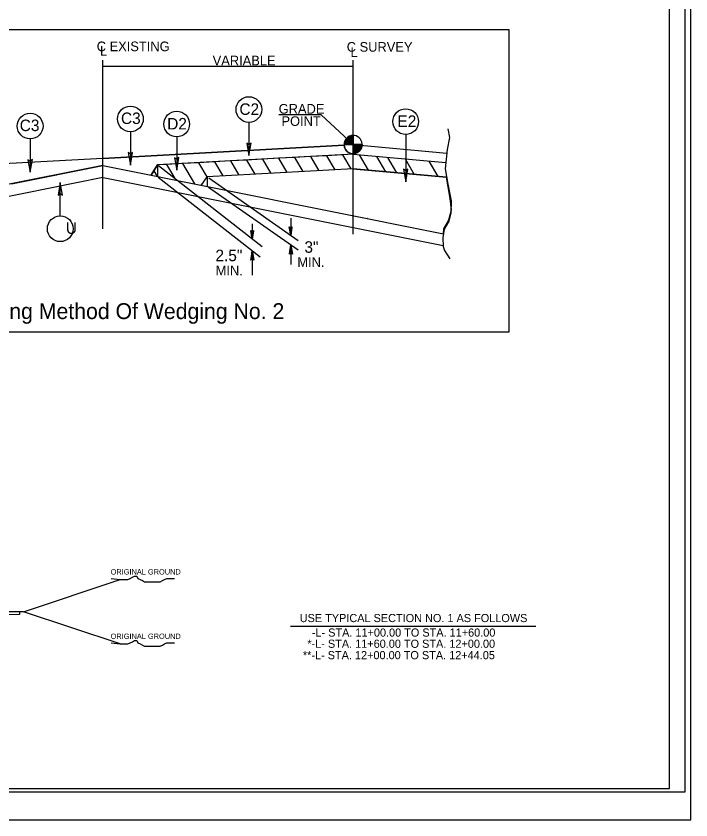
# Model space of a CAD drawing. Extents: x 957297 to 961629, y 830661 to 840840.
# Drawn here: x 959856 to 960395, y 839740 to 840382 of the extents above; entities that cross this region are included whole.
import ezdxf

# ---------------------------------------------------------------- set-up
doc = ezdxf.new("R2010")
doc.units = 0
for name, color, linetype in [('Old_Level_1', 7, 'Continuous'), ('Old_Level_21', 7, 'Continuous'), ('Sheet Plot Border Inside CELL', 7, 'Continuous'), ('Sheet Plot Border Outside CELL', 7, 'Continuous'), ('Sheet Typical CELL', 7, 'Continuous'), ('Typical Detail Wedge1 CELL', 7, 'Continuous'), ('Typical Grade Point Symbol CELL', 7, 'Continuous'), ('Typical ID Circle CELL', 7, 'Continuous'), ('Typical Terminator CELL', 7, 'Continuous'), ('Typical Text Centerline CELL', 7, 'Continuous'), ('Typical Text General CELL', 7, 'Continuous'), ('Typical Text Grade Point CELL', 7, 'Continuous'), ('Typical Text ID Circle CELL', 7, 'Continuous')]:
    doc.layers.add(name, color=color, linetype=linetype)

msp = doc.modelspace()

# ---------------------------------------------------------------- linework, layer by layer
at = {"layer": 'Old_Level_1'}
for p, q in [((959861.75, 839906), (959938.93, 839931.73)), ((959861.75, 839906), (959798.79, 839905.37)), ((959858.45, 839903.79), (959825.43, 839903.46)), ((959858.45, 839905.97), (959858.45, 839903.79)), ((959938.93, 839880.27), (959861.75, 839906)), ((960075.05, 839894.58), (960270.99, 839894.58))]:
    msp.add_line(p, q, dxfattribs=at)
msp.add_lwpolyline([(960249.58, 840370.75), (959623.52, 840370.75), (959623.52, 840129.62), (960249.58, 840129.62)], close=True, dxfattribs=at)
at = {"layer": 'Old_Level_21'}
for points in [[(959931.84, 839932.61), (959938.93, 839931.73), (959940.71, 839931.73), (959943.37, 839931.73), (959945.15, 839931.73), (959946.92, 839932.61), (959948.69, 839933.51), (959950.46, 839934.39), (959952.24, 839934.39), (959953.14, 839932.61), (959954.9, 839931.73), (959956.68, 839930.84), (959958.45, 839929.96), (959960.22, 839929.96), (959961.99, 839929.96), (959963.77, 839929.96), (959965.54, 839929.96), (959967.32, 839929.96), (959969.09, 839929.96), (959970.86, 839929.96), (959972.63, 839930.84), (959974.4, 839931.73), (959976.17, 839932.61), (959978.85, 839932.61), (959980.62, 839932.61), (959982.39, 839932.61)], [(959931.84, 839881.15), (959938.93, 839880.27), (959940.71, 839880.27), (959943.37, 839880.27), (959945.15, 839880.27), (959946.92, 839881.15), (959948.69, 839882.05), (959950.46, 839882.93), (959952.24, 839882.93), (959953.14, 839881.15), (959954.9, 839880.27), (959956.68, 839879.37), (959958.45, 839878.5), (959960.22, 839878.5), (959961.99, 839878.5), (959963.77, 839878.5), (959965.54, 839878.5), (959967.32, 839878.5), (959969.09, 839878.5), (959970.86, 839878.5), (959972.63, 839879.37), (959974.4, 839880.27), (959976.17, 839881.15), (959978.85, 839881.15), (959980.62, 839881.15), (959982.39, 839881.15)]]:
    msp.add_lwpolyline(points, dxfattribs=at)
at = {"layer": 'Sheet Plot Border Inside CELL'}
msp.add_lwpolyline([(960390.3, 840817.27), (958723.8, 840817.27), (958723.8, 839762.17), (960390.3, 839762.17)], close=True, dxfattribs=at)
at = {"layer": 'Sheet Plot Border Outside CELL'}
msp.add_lwpolyline([(960394.8, 840839.72), (958710.8, 840839.72), (958710.8, 839739.72), (960394.8, 839739.72)], close=True, dxfattribs=at)
at = {"layer": 'Sheet Typical CELL'}
msp.add_lwpolyline([(960377.8, 840814.72), (958877.8, 840814.72), (958877.8, 839764.72), (960377.8, 839764.72)], close=True, dxfattribs=at)
at = {"layer": 'Typical Detail Wedge1 CELL'}
for p, q in [((959925.21, 840211.84), (959925.21, 840346.6)), ((960125.03, 840279.09), (960125.03, 840346.65)), ((960125.03, 840341.47), (959925.21, 840341.47)), ((960117.75, 840278.69), (959925.21, 840268.1)), ((959925.21, 840268.1), (960117.75, 840278.69)), ((960125.03, 840279.09), (960125.02, 840271.39)), ((960125.03, 840279.09), (960199.77, 840272.36)), ((959925.21, 840268.1), (959692.59, 840255.33)), ((959925.21, 840268.1), (959692.59, 840255.33)), ((959925.21, 840262.34), (959925.21, 840268.1)), ((959925.21, 840262.34), (959925.21, 840268.1)), ((960125.02, 840271.39), (959968.84, 840262.81)), ((960052.72, 840267.42), (960039.94, 840266.72)), ((960065.5, 840268.13), (960052.72, 840267.42)), ((960052.72, 840267.42), (960059.3, 840256.14)), ((960078.27, 840268.82), (960065.5, 840268.13)), ((960065.5, 840268.13), (960072.08, 840256.84)), ((960091.05, 840269.53), (960078.27, 840268.82)), ((960078.27, 840268.82), (960084.86, 840257.55)), ((960103.82, 840270.24), (960091.05, 840269.53)), ((960091.05, 840269.53), (960097.63, 840258.25)), ((960116.6, 840270.93), (960103.82, 840270.24)), ((960103.82, 840270.24), (960110.41, 840258.96)), ((960125.02, 840271.39), (960116.6, 840270.93)), ((960116.6, 840270.93), (960123.17, 840259.65)), ((960124.98, 840271.93), (960125.02, 840271.39)), ((960125.02, 840271.39), (960198.98, 840264.74)), ((960125.02, 840271.39), (960198.96, 840264.74)), ((960125.03, 840207.61), (960125.03, 840271.93)), ((960129.76, 840270.96), (960136.96, 840258.62)), ((960143.68, 840269.71), (960150.89, 840257.36)), ((960152.56, 840268.92), (960159.75, 840256.6)), ((960166.49, 840267.66), (960173.7, 840255.3)), ((959925.21, 840262.34), (959697.32, 840216.87)), ((959852.13, 840247.71), (959925.21, 840262.34)), ((959925.21, 840262.34), (960197.19, 840207.94)), ((959963.55, 840254.54), (959968.84, 840262.81)), ((959968.84, 840262.81), (959963.62, 840254.65)), ((959976.07, 840263.22), (959968.84, 840262.81)), ((959968.84, 840262.81), (959968.84, 840253.61)), ((959969.46, 840262.28), (960052.28, 840197.58)), ((959988.84, 840263.91), (959976.07, 840263.22)), ((959976.07, 840263.22), (959983.36, 840250.71)), ((960001.62, 840264.6), (959988.84, 840263.91)), ((959988.84, 840263.91), (959998.29, 840247.73)), ((960014.38, 840265.31), (960001.62, 840264.6)), ((960001.62, 840264.6), (960008.2, 840253.34)), ((960027.17, 840266.02), (960014.38, 840265.31)), ((960014.38, 840265.31), (960020.97, 840254.03)), ((960039.94, 840266.72), (960027.17, 840266.02)), ((960027.17, 840266.02), (960033.74, 840254.74)), ((960039.94, 840266.72), (960046.53, 840255.44)), ((960185.43, 840265.95), (960192.63, 840253.6)), ((959965.85, 840258.15), (959968.44, 840253.7)), ((960125.03, 840259.76), (960008.46, 840253.34)), ((960125.03, 840259.76), (960008.47, 840253.34)), ((960124.86, 840259.7), (960199.69, 840252.96)), ((960199.69, 840252.96), (960125.03, 840259.76)), ((959925.21, 840252.71), (959697.03, 840207.06)), ((959925.42, 840252.71), (960196.8, 840198.43)), ((959969.39, 840253.13), (960050.75, 840189.56)), ((960003.6, 840246.49), (960008.47, 840253.34)), ((960008.46, 840253.34), (960008.46, 840245.69)), ((960009.68, 840252.5), (960081.22, 840202.41)), ((960202.54, 840236.15), (960199.69, 840252.96)), ((960009.44, 840245.19), (960081.1, 840195)), ((960203.58, 840226.88), (960202.54, 840236.15)), ((960201.51, 840218.98), (960203.58, 840226.88)), ((960044.46, 840215.76), (960044.46, 840203.68)), ((960075.22, 840220.34), (960075.22, 840206.61)), ((960197.39, 840212.12), (960201.51, 840218.98)), ((960044.46, 840203.68), (960043.26, 840210.44)), ((960043.26, 840210.44), (960044.46, 840209.56)), ((960043.43, 840210.31), (960044.46, 840203.68)), ((960044.46, 840203.68), (960043.61, 840210.18)), ((960043.78, 840210.07), (960044.46, 840203.68)), ((960044.46, 840203.68), (960043.95, 840209.94)), ((960044.12, 840209.81), (960044.46, 840203.68)), ((960044.46, 840203.68), (960044.29, 840209.68)), ((960044.46, 840203.68), (960045.65, 840210.44)), ((960044.46, 840209.56), (960045.65, 840210.44)), ((960044.46, 840203.68), (960045.48, 840210.31)), ((960045.31, 840210.18), (960044.46, 840203.68)), ((960044.46, 840203.68), (960045.14, 840210.07)), ((960044.97, 840209.94), (960044.46, 840203.68)), ((960044.46, 840203.68), (960044.8, 840209.81)), ((960044.62, 840209.68), (960044.46, 840203.68)), ((960044.46, 840209.56), (960044.46, 840203.68)), ((960075.22, 840206.61), (960074.02, 840213.37)), ((960074.02, 840213.37), (960075.22, 840212.5)), ((960074.19, 840213.25), (960075.22, 840206.61)), ((960075.22, 840206.61), (960074.36, 840213.12)), ((960074.53, 840213), (960075.22, 840206.61)), ((960075.22, 840206.61), (960074.71, 840212.86)), ((960074.87, 840212.75), (960075.22, 840206.61)), ((960075.22, 840206.61), (960075.05, 840212.63)), ((960075.22, 840206.61), (960076.41, 840213.37)), ((960075.22, 840212.5), (960076.41, 840213.37)), ((960075.22, 840206.61), (960076.24, 840213.25)), ((960076.07, 840213.12), (960075.22, 840206.61)), ((960075.22, 840206.61), (960075.9, 840213)), ((960075.73, 840212.86), (960075.22, 840206.61)), ((960075.22, 840206.61), (960075.56, 840212.75)), ((960075.39, 840212.63), (960075.22, 840206.61)), ((960075.22, 840212.5), (960075.22, 840206.61)), ((960197.19, 840207.94), (960197.39, 840212.12)), ((960075.22, 840199.12), (960073.88, 840191.51)), ((960075.22, 840199.12), (960074.06, 840191.66)), ((960074.26, 840191.8), (960075.22, 840199.12)), ((960075.22, 840199.12), (960074.46, 840191.95)), ((960074.65, 840192.08), (960075.22, 840199.12)), ((960075.22, 840199.12), (960074.83, 840192.22)), ((960075.03, 840192.35), (960075.22, 840199.12)), ((960075.22, 840199.12), (960076.56, 840191.53)), ((960076.37, 840191.66), (960075.22, 840199.12)), ((960075.22, 840199.12), (960076.18, 840191.8)), ((960075.99, 840191.95), (960075.22, 840199.12)), ((960075.22, 840199.12), (960075.79, 840192.08)), ((960075.61, 840192.22), (960075.22, 840199.12)), ((960075.22, 840199.12), (960075.41, 840192.37)), ((960075.22, 840192.51), (960075.22, 840199.12)), ((960075.22, 840199.12), (960075.22, 840183.29)), ((960044.46, 840194.48), (960043.11, 840186.88)), ((960044.46, 840194.48), (960043.31, 840187.01)), ((960043.5, 840187.15), (960044.46, 840194.48)), ((960044.46, 840194.48), (960043.69, 840187.3)), ((960043.88, 840187.43), (960044.46, 840194.48)), ((960044.46, 840194.48), (960044.07, 840187.57)), ((960044.26, 840187.72), (960044.46, 840194.48)), ((960044.46, 840194.48), (960045.81, 840186.88)), ((960045.61, 840187.01), (960044.46, 840194.48)), ((960044.46, 840194.48), (960045.41, 840187.15)), ((960045.22, 840187.3), (960044.46, 840194.48)), ((960044.46, 840194.48), (960045.04, 840187.43)), ((960044.84, 840187.57), (960044.46, 840194.48)), ((960044.46, 840194.48), (960044.65, 840187.72)), ((960044.46, 840187.86), (960044.46, 840194.48)), ((960044.46, 840194.48), (960044.46, 840174.94)), ((960075.22, 840192.51), (960073.88, 840191.51)), ((960076.56, 840191.53), (960075.22, 840192.51)), ((960044.46, 840187.86), (960043.11, 840186.88)), ((960045.81, 840186.88), (960044.46, 840187.86))]:
    msp.add_line(p, q, dxfattribs=at)
msp.add_lwpolyline([(960200.69, 840291.56), (960201.92, 840284.84), (960200.08, 840275.24), (960198.45, 840259.73), (960200.69, 840247.5), (960203.34, 840234.24), (960203.14, 840224.24), (960201.5, 840217.92), (960197.83, 840211.59), (960196.61, 840204.65), (960196.82, 840197.72), (960198.04, 840194.46), (960202.32, 840187.94)], dxfattribs=at)
msp.add_arc((960136.28, 840219.93), 0.207, 53.42542, 104.24171, dxfattribs=at)
at = {"layer": 'Typical Grade Point Symbol CELL'}
for p, q in [((960124.98, 840279.17), (960124.98, 840286.41)), ((960117.73, 840279.17), (960124.98, 840279.17)), ((960124.98, 840271.93), (960124.98, 840279.17)), ((960132.23, 840279.17), (960124.98, 840279.17)), ((960124.98, 840279.17), (960124.98, 840271.93)), ((960125.03, 840271.93), (960125.03, 840279.09))]:
    msp.add_line(p, q, dxfattribs=at)
for points in [[(960122.89, 840286.1), (960122.89, 840279.17)], [(960123.02, 840286.15), (960123.02, 840279.17)], [(960123.17, 840286.19), (960123.17, 840279.17)], [(960123.31, 840286.22), (960123.31, 840279.17)], [(960123.46, 840286.26), (960123.46, 840279.17)], [(960123.61, 840286.28), (960123.61, 840279.17)], [(960123.76, 840286.31), (960123.76, 840279.17)], [(960123.9, 840286.33), (960123.9, 840279.17)], [(960124.04, 840286.36), (960124.04, 840279.17)], [(960124.19, 840286.37), (960124.19, 840279.17)], [(960124.32, 840286.39), (960124.32, 840279.17)], [(960124.48, 840286.4), (960124.48, 840279.17)], [(960124.62, 840286.41), (960124.62, 840279.17)], [(960124.77, 840286.41), (960124.77, 840279.17)], [(960124.92, 840286.41), (960124.92, 840286.41), (960124.92, 840279.17)], [(960117.81, 840280.19), (960117.81, 840279.17)], [(960117.95, 840280.94), (960117.95, 840279.16)], [(960118.1, 840281.43), (960118.1, 840279.16)], [(960118.24, 840281.83), (960118.24, 840279.17)], [(960118.39, 840282.17), (960118.39, 840279.16)], [(960118.53, 840282.48), (960118.53, 840279.16)], [(960118.68, 840282.75), (960118.68, 840279.17)], [(960118.83, 840282.98), (960118.83, 840279.16)], [(960118.96, 840283.22), (960118.96, 840279.16)], [(960119.11, 840283.42), (960119.12, 840279.17)], [(960119.25, 840283.61), (960119.25, 840279.16)], [(960119.4, 840283.79), (960119.4, 840279.16)], [(960119.55, 840283.96), (960119.55, 840279.17)], [(960119.7, 840284.13), (960119.7, 840279.16)], [(960119.84, 840284.28), (960119.84, 840279.16)], [(960119.98, 840284.41), (960119.98, 840279.17)], [(960120.12, 840284.55), (960120.13, 840279.16)], [(960120.27, 840284.68), (960120.27, 840279.17)], [(960120.42, 840284.8), (960120.42, 840279.17)], [(960120.56, 840284.91), (960120.56, 840279.17)], [(960120.71, 840285.01), (960120.71, 840279.17)], [(960120.86, 840285.12), (960120.86, 840279.17)], [(960120.99, 840285.22), (960120.99, 840279.17)], [(960121.14, 840285.31), (960121.14, 840279.17)], [(960121.28, 840285.39), (960121.28, 840279.17)], [(960121.43, 840285.48), (960121.43, 840279.17)], [(960121.58, 840285.56), (960121.58, 840279.17)], [(960121.73, 840285.65), (960121.73, 840279.17)], [(960121.87, 840285.72), (960121.87, 840279.17)], [(960122.01, 840285.77), (960122.01, 840279.17)], [(960122.15, 840285.84), (960122.16, 840279.17)], [(960122.29, 840285.9), (960122.29, 840279.17)], [(960122.45, 840285.96), (960122.45, 840279.17)], [(960122.59, 840286.01), (960122.59, 840279.17)], [(960122.74, 840286.06), (960122.74, 840279.17)], [(960125.08, 840279.17), (960125.08, 840271.93), (960125.08, 840271.93)], [(960125.24, 840279.17), (960125.24, 840271.93)], [(960125.37, 840279.17), (960125.38, 840271.93)], [(960125.52, 840279.17), (960125.52, 840271.94)], [(960125.66, 840279.17), (960125.67, 840271.95)], [(960125.8, 840279.17), (960125.8, 840271.98)], [(960125.96, 840279.17), (960125.96, 840271.99)], [(960126.1, 840279.17), (960126.1, 840272.02)], [(960126.25, 840279.17), (960126.25, 840272.04)], [(960126.39, 840279.17), (960126.4, 840272.06)], [(960126.54, 840279.17), (960126.54, 840272.1)], [(960126.67, 840279.17), (960126.68, 840272.12)], [(960126.82, 840279.17), (960126.82, 840272.16)], [(960126.97, 840279.17), (960126.97, 840272.21)], [(960127.11, 840279.17), (960127.11, 840272.25)], [(960127.27, 840279.17), (960127.27, 840272.29)], [(960127.4, 840279.17), (960127.4, 840272.33)], [(960127.55, 840279.17), (960127.55, 840272.4)], [(960127.69, 840279.17), (960127.7, 840272.45)], [(960127.83, 840279.17), (960127.83, 840272.5)], [(960127.98, 840279.17), (960127.98, 840272.58)], [(960128.13, 840279.17), (960128.13, 840272.64)], [(960128.28, 840279.17), (960128.28, 840272.71)], [(960128.42, 840279.17), (960128.42, 840272.79)], [(960128.57, 840279.17), (960128.57, 840272.86)], [(960128.7, 840279.17), (960128.71, 840272.95)], [(960128.85, 840279.17), (960128.85, 840273.04)], [(960129, 840279.17), (960129, 840273.14)], [(960129.14, 840279.17), (960129.14, 840273.24)], [(960129.29, 840279.17), (960129.29, 840273.35)], [(960129.44, 840279.17), (960129.44, 840273.46)], [(960129.58, 840279.17), (960129.58, 840273.56)], [(960129.72, 840279.17), (960129.73, 840273.68)], [(960129.86, 840279.17), (960129.86, 840273.81)], [(960130.01, 840279.17), (960130.01, 840273.96)], [(960130.16, 840279.17), (960130.16, 840274.1)], [(960130.31, 840279.17), (960130.31, 840274.24)], [(960130.45, 840279.17), (960130.45, 840274.4)], [(960130.6, 840279.17), (960130.6, 840274.58)], [(960130.73, 840279.17), (960130.73, 840274.77)], [(960130.88, 840279.17), (960130.88, 840274.95)], [(960131.03, 840279.17), (960131.03, 840275.17)], [(960131.17, 840279.17), (960131.17, 840275.4)], [(960131.32, 840279.17), (960131.32, 840275.65)], [(960131.47, 840279.17), (960131.47, 840275.93)], [(960131.61, 840279.17), (960131.61, 840276.22)], [(960131.75, 840279.17), (960131.75, 840276.58)], [(960131.89, 840279.17), (960131.89, 840277.01)], [(960132.04, 840279.17), (960132.04, 840277.53)], [(960132.19, 840279.17), (960132.19, 840278.38)]]:
    msp.add_lwpolyline(points, dxfattribs=at)
for start, end in [(90.00952, 180.00952), (183.82869, 181.99966), (183.84069, 269.98142), (271.28136, 0.00952), (270.00952, 270.34666)]:
    msp.add_arc((960124.98, 840279.17), 7.25, start, end, dxfattribs=at)
at = {"layer": 'Typical ID Circle CELL'}
for p, q in [((960041.73, 840296.84), (960041.73, 840270.29)), ((959947.12, 840289.31), (959947.12, 840262.76)), ((960166.98, 840287.19), (960166.98, 840249.45)), ((959867.04, 840283.63), (959867.04, 840257.08)), ((959984.1, 840285.25), (959984.1, 840258.7)), ((959891.08, 840222.16), (959891.08, 840248.71))]:
    msp.add_line(p, q, dxfattribs=at)
for centre in [(960041.73, 840307.11), (959947.12, 840299.58), (959984.1, 840295.52), (960166.97, 840297.46), (959867.04, 840293.9), (959891.08, 840211.89)]:
    msp.add_circle(centre, 10.27, dxfattribs=at)
at = {"layer": 'Typical Terminator CELL'}
for points in [[(960040.02, 840280.25), (960041.73, 840270.29), (960043.5, 840280.31), (960041.73, 840279.03)], [(959865.32, 840267.04), (959867.04, 840257.08), (959868.81, 840267.1), (959867.04, 840265.82)], [(959945.41, 840272.72), (959947.12, 840262.76), (959948.89, 840272.78), (959947.12, 840271.5)], [(959982.38, 840268.66), (959984.1, 840258.7), (959985.87, 840268.72), (959984.1, 840267.45)], [(959982.38, 840268.66), (959984.1, 840258.7), (959985.87, 840268.72), (959984.1, 840267.45)], [(960165.26, 840259.41), (960166.98, 840249.45), (960168.75, 840259.46), (960166.98, 840258.19)], [(959892.8, 840238.75), (959891.08, 840248.71), (959889.31, 840238.7), (959891.08, 840239.97)]]:
    msp.add_lwpolyline(points, close=True, dxfattribs=at)
at = {"layer": 'Typical Text Grade Point CELL'}
for q in [(960065.55, 840302.87), (960125.03, 840279.09)]:
    msp.add_line((960099.45, 840302.87), q, dxfattribs=at)

# ---------------------------------------------------------------- texts
at = {"layer": 'Old_Level_1'}
for s, p in [('USE TYPICAL SECTION NO. 1 AS FOLLOWS', (960082.34, 839897.71)), ('-L- STA. 11+00.00 TO STA. 11+60.00', (960092.02, 839886.12)), ('*-L- STA. 11+60.00 TO STA. 12+00.00', (960088.42, 839877.18)), ('**-L- STA. 12+00.00 TO STA. 12+44.05', (960084.88, 839868.07))]:
    msp.add_text(s, height=6.5088, dxfattribs=at).set_placement(p)
at = {"layer": 'Old_Level_21'}
for p in [(959931.3, 839935.73), (959931.3, 839884.26)]:
    msp.add_text('ORIGINAL GROUND', height=4.2722, dxfattribs=at).set_placement(p)
at = {"layer": 'Typical Detail Wedge1 CELL'}
for s, p in [('VARIABLE', (960012.82, 840342.41)), ('MIN.', (960080.48, 840181.38)), ('MIN.', (960015.24, 840174.68))]:
    msp.add_text(s, height=7.683, dxfattribs=at).set_placement(p)
at = {"layer": 'Typical Text Centerline CELL'}
for s, height, p in [('C EXISTING', 7.683, (959920.22, 840353.71)), ('L', 7.68, (959922.89, 840350.06)), ('C SURVEY', 7.683, (960119.91, 840353.29)), ('L', 7.68, (960122.88, 840349.04))]:
    msp.add_text(s, height=height, dxfattribs=at).set_placement(p)
at = {"layer": 'Typical Text General CELL'}
msp.add_text('Detail Showing Method Of Wedging No. 2', height=12.6816, dxfattribs=at).set_placement((959756.13, 840139.75))
at = {"layer": 'Typical Text Grade Point CELL'}
for s, p in [('GRADE', (960065.53, 840303.82)), ('POINT', (960067.77, 840294.01))]:
    msp.add_text(s, height=7.683, dxfattribs=at).set_placement(p)
at = {"layer": 'Typical Text ID Circle CELL'}
for s, p in [('C2', (960034.2, 840302.82)), ('C3', (959858.73, 840289.87)), ('C3', (959939.6, 840295.54)), ('D2', (959976.51, 840291.18)), ('E2', (960160.41, 840293.2)), ('3"', (960086.1, 840192.69)), ('2.5"', (960015.05, 840185.99))]:
    msp.add_text(s, height=9.194, dxfattribs=at).set_placement(p)
msp.add_text('U', height=9.19, rotation=360, dxfattribs=at).set_placement((959895.57, 840207.82))

doc.saveas('drawing.dxf')
